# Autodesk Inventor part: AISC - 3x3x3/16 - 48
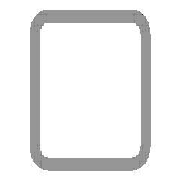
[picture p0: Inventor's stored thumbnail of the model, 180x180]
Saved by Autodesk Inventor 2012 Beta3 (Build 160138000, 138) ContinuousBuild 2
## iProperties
Created: 2011-01
Part Number: AISC - 3x3x3/16 - 48
Material: Steel, Mild
Description: Tube
Document SubType Name: Modeling
Standard: ANSI
Designer: Beta-8540w
Standards Organization: ANSI
Language: en-US
Size Designation: 3x3x3/16
Categories: <MemberInstance><Categories><Category DisplayName="Structural Shapes" InternalName="089c4875-fa83-4c05-b084-43b9cc11f5ed" Mnemonic="GRDR"><CategoryParameter Dis
Stock Number: 3x3x3/16
Density: 7.86 g/cm^3
IsCustomPart: 1
_CCFamilyMember: 9
_CCFamilyDisplayName: ANSI AISC (Square) - Tube
_FrameMemberDoc: Frame Member File
_Version: 15.0.0
_GetPNFromCC: 1
G_L: 48.000 in
G_W: 3.000 in
G_H: 3.000 in
Author: Beta-8540w
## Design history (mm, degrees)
node "Start plane"
node "End plane"
sketch "Sketch"
  geometry: L1 (-38.1, -28.575)-(-38.1, 28.575); L2 (-28.575, 38.1)-(28.575, 38.1); L3 (38.1, 28.575)-(38.1, -28.575); L4 (28.575, -38.1)-(-28.575, -38.1); L5 (-28.575, 33.337)-(28.575, 33.338); L6 (33.338, 28.575)-(33.338, -28.575); L7 (28.575, -33.337)-(-28.575, -33.338); L8 (-33.338, -28.575)-(-33.338, 28.575); L9 (0, 56.102)-(0, -56.102) reference; L10 (-56.102, 0)-(56.102, 0) reference; A1 r 9.525 centre (-28.575, -28.575) between (-38.1, -28.575) and (-28.575, -38.1); A2 r 9.525 centre (-28.575, 28.575) between (-28.575, 38.1) and (-38.1, 28.575); A3 r 9.525 centre (28.575, 28.575) between (38.1, 28.575) and (28.575, 38.1); A4 r 9.525 centre (28.575, -28.575) between (28.575, -38.1) and (38.1, -28.575); A5 r 4.763 centre (-28.575, 28.575) between (-28.575, 33.337) and (-33.338, 28.575); A6 r 4.763 centre (28.575, 28.575) between (33.338, 28.575) and (28.575, 33.338); A7 r 4.763 centre (28.575, -28.575) between (28.575, -33.337) and (33.338, -28.575); A8 r 4.763 centre (-28.575, -28.575) between (-33.338, -28.575) and (-28.575, -33.338)
  constraints: 16 end point, 16 point on circle, 8 centre point, 8 tangent, 4 parallel, 3 equal radius, 2 perpendicular, 7 other
  dimensions: "d10" = 76.2 distance between parallel lines of L2 L4 (= G_H); "d11" = 76.2 distance between parallel lines of L1 L3 (= G_W); "d12" = 4.7625 distance between parallel lines of L3 L6 (= G_T); "d15" = 38.1 distance between parallel lines of L2 L10 (= 0.5 x d10); "d16" = 38.1 distance between parallel lines of L9 L3 (= 0.5 x d11); "d17" = 9.525 radius of A1 (= G_IR)
extrude "Body" new body sketch "Sketch" stored distance "d3" = 1219.2 (= G_L); taper "d4" = 0 deg
node "Driven Length"
  sketch "Sketch3"
    geometry: L1 (0, 0)-(10, 0) reference
    constraints: 2 end point, 1 horizontal
  workplane "Work Plane3"
  sketch "Sketch4"
    geometry: L1 (-2, 0)-(12, 0) reference; L2 (-2, 1219.2)-(12, 1219.2) reference
    dimensions: "d19" = 1219.2 distance between parallel lines of L1 L2 (derived)
body "Solid1"
other parameters: "G_W" = 76.2 [user parameter; used in 1 equation term], "G_H" = 76.2 [user parameter; used in 1 equation term], "G_T" = 4.7625 [user parameter; used in 1 equation term], "G_IR" = 9.525 [user parameter; used in 1 equation term], "G_L" = 1219.2 (= d19) [user parameter; used in 1 equation term], "G_OFFSET_START" = 0 [user parameter; used in 1 equation term], "G_OFFSET_END" = 0 [user parameter; used in 1 equation term], "d13" = 0 (computed from G_OFFSET_START), "d14" = 1219.2 (= G_OFFSET_END + B_L), "B_L" = 1219.2 [user parameter; used in 1 equation term], "d18" = 90 deg
